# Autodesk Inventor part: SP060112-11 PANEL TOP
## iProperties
Created: 2012-06
Part Number: SP060112-11 PANEL TOP
Material: Polycarbonate, Clear
Document SubType Name: Modeling
Designer: Administrator
Mass: 4522.83 g
Surface Area: 13673.4 cm^2
Volume: 3769.03 cm^3
Density: 1.2 g/cm^3
Author: Administrator
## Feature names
1. Extrusion1
